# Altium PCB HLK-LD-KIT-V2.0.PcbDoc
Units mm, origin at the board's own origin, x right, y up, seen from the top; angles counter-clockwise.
Board outline 40.5 x 27.7 mm, 2 copper layers (Top Layer, Bottom Layer); 31 components, 15 nets, 118 pads, 48 vias.
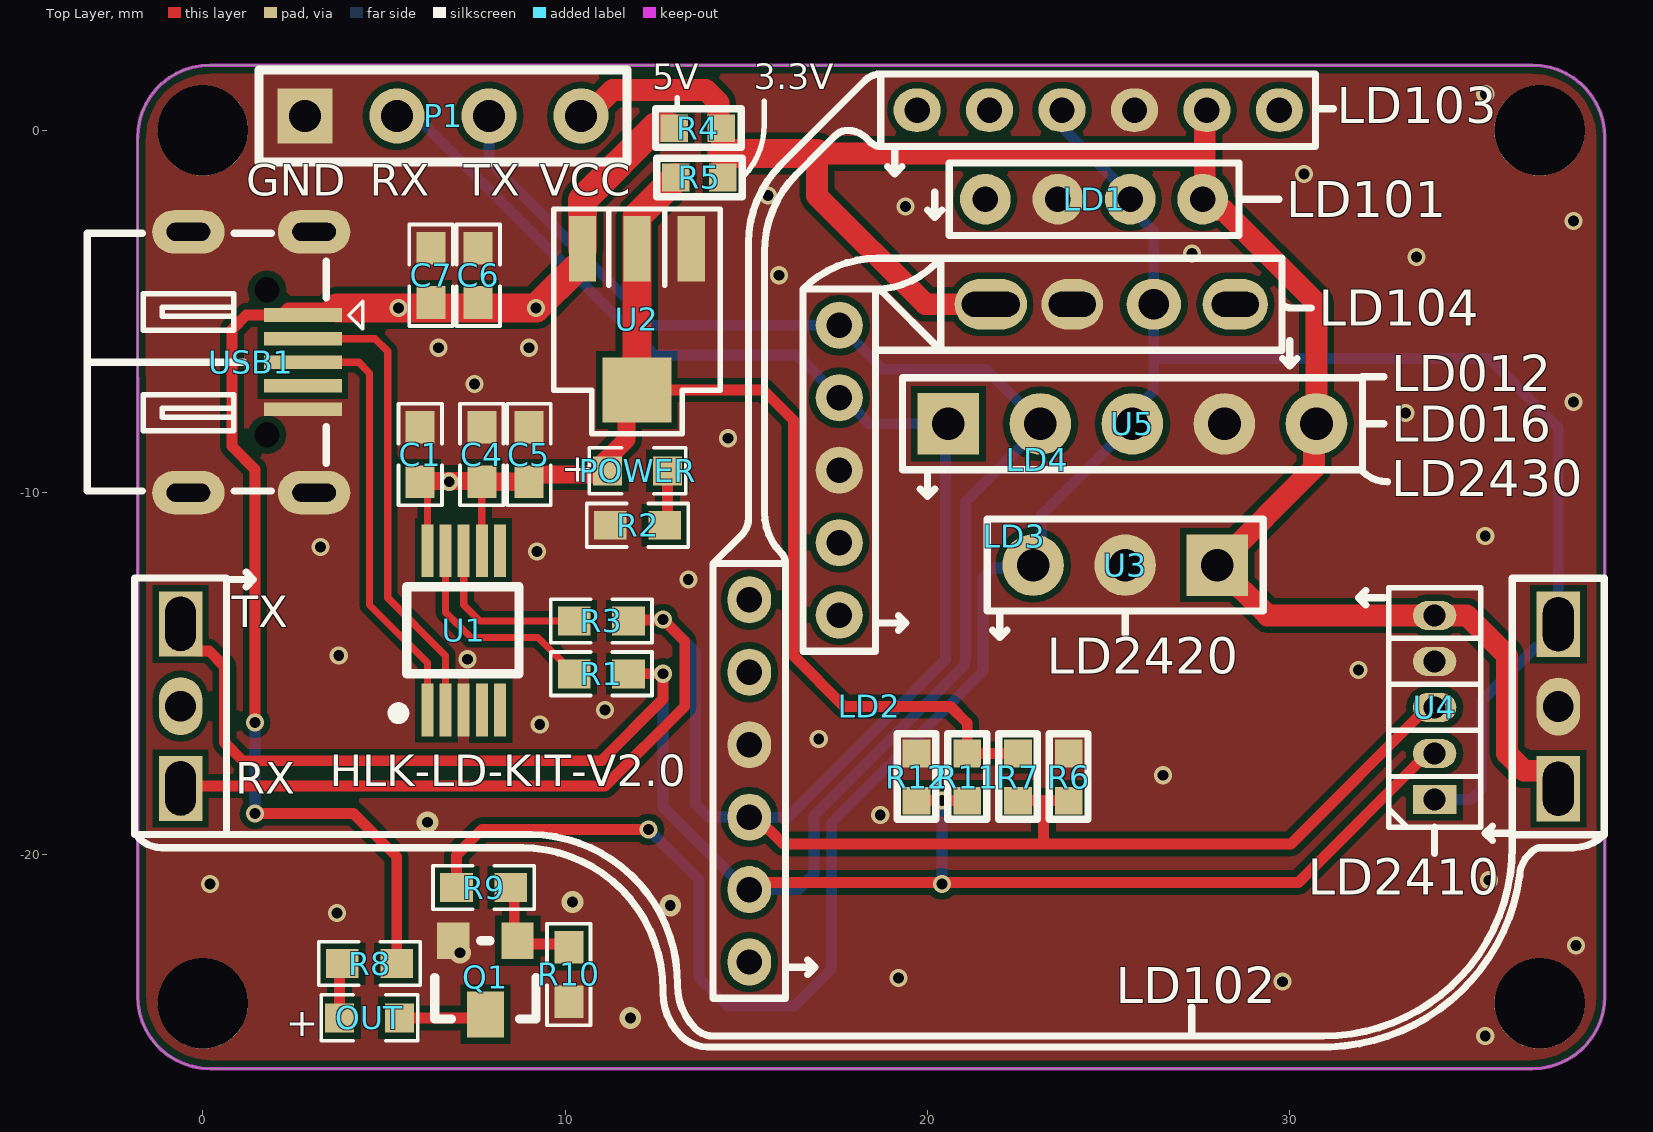
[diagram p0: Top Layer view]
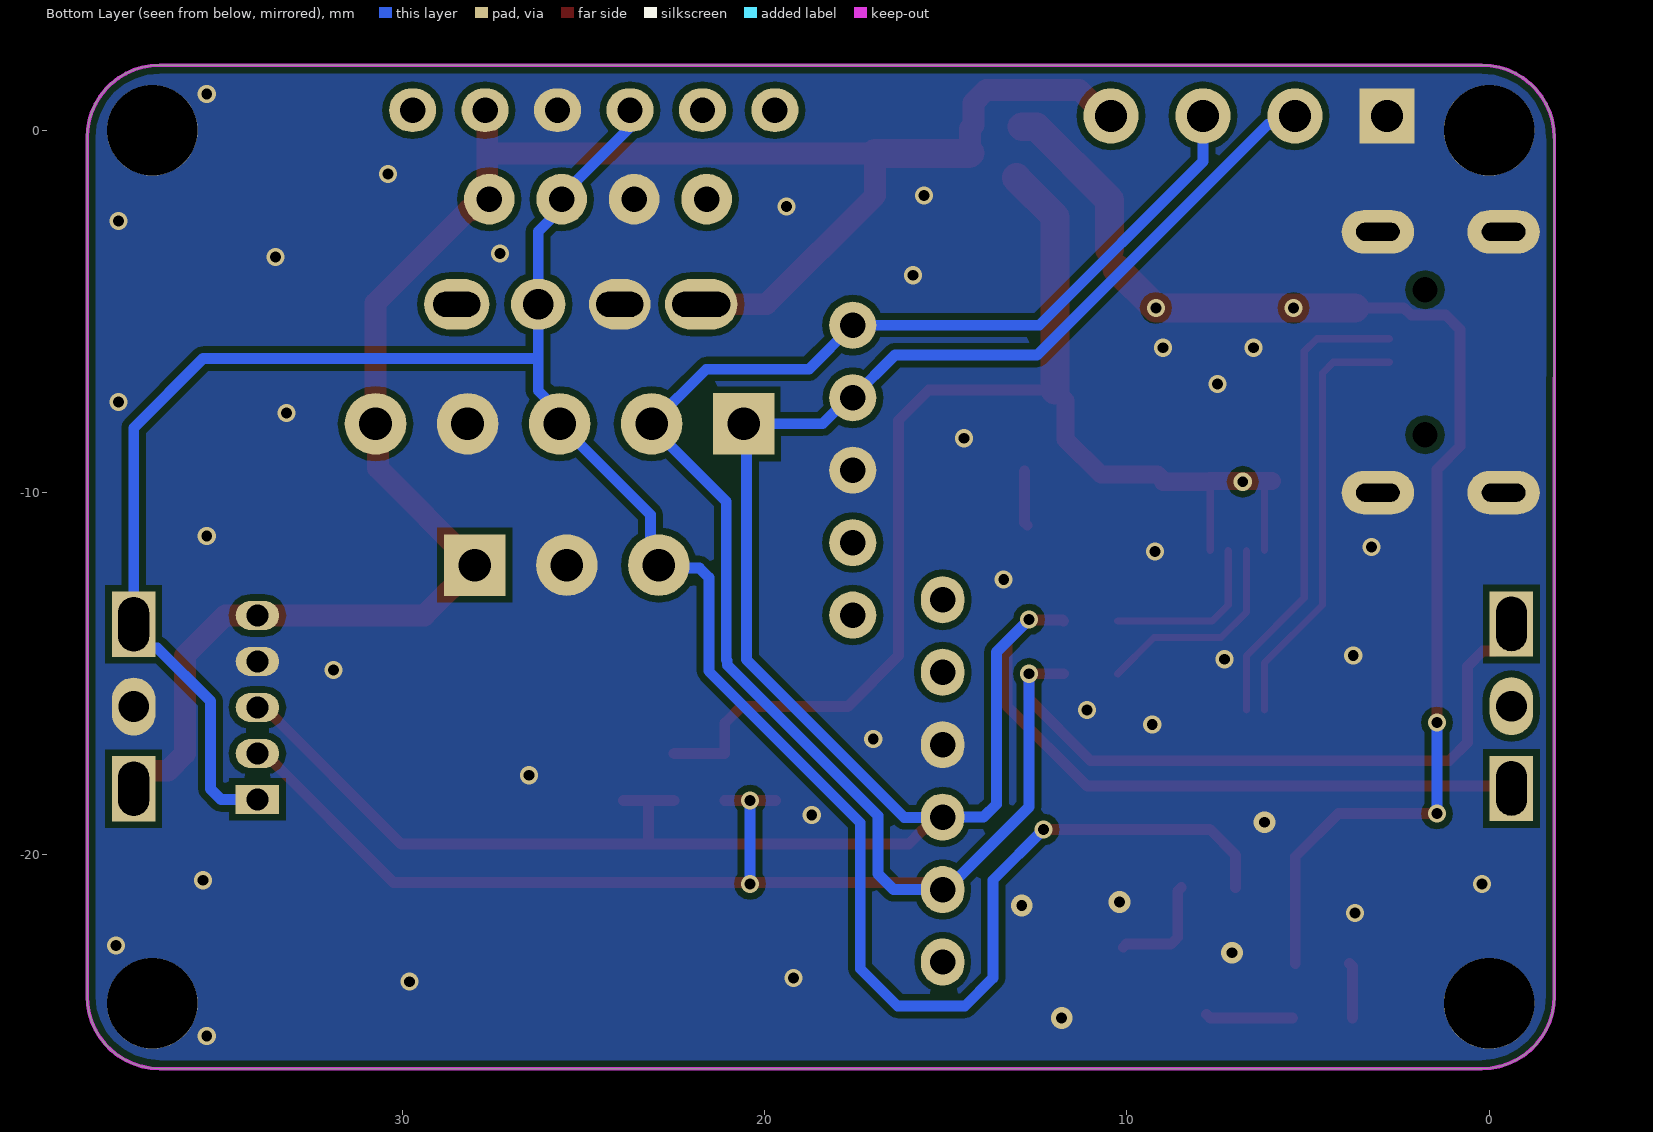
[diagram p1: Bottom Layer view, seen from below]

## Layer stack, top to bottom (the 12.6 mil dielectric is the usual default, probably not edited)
Top Solder: solder mask 0.0102, Solder Resist, Dk 3.5
Top Layer: signal copper 0.0356
Dielectric1: dielectric 0.32, FR-4, Dk 4.8
Bottom Layer: signal copper 0.0356
Bottom Solder: solder mask 0.0102, Solder Resist, Dk 3.5

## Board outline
-1.8,-23.9 -1.8,-0.2 cw(c0.2,-0.2) 0.2,1.8 36.7,1.8 cw(c36.7,-0.2) 38.7,-0.2 38.7,-23.9 cw(c36.7,-23.9) 36.7,-25.9 0.2,-25.9 cw(c0.2,-23.9)

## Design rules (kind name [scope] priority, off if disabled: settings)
Clearance [All] p1: gap=0.18 ignorepadtopadclearanceinfootprint=FALSE except(0: Arc-Hole Track-Hole SMDPad-Hole THPad-Hole Via-Hole Fill-Hole Poly-Hole Region-Hole Text-Hole)
FabricationTestPointUsage TestPointUsage [All] p1: valid=0 allowmultiple=FALSE
FabricationTestpoint Testpoint [(IsPad And (OnTopLayer Or OnBottomLayer))] p1: side=3 testpointundercomponent=TRUE minsize=1.016 maxsize=2.54 preferedsize=1.524 minholesize=0 maxholesize=1.016 preferedholesize=0.813 testpointgrid=0.025 allowsidetop=TRUE allowsidebottom=TRUE usegrid=TRUE gridtolerance=0
PolygonConnect [All] p1: connectstyle=Direct reliefconductorwidth=0.254 reliefentries=4 polygonreliefangle="90 Angle" airgapwidth=0.254
RoutingVias [All] p1: holewidth=0.3 width=0.5 viastyle="Through Hole" minholewidth=0.3 minwidth=0.5 maxholewidth=0.711 maxwidth=1.27
SilkToSolderMaskClearance SilkscreenOverComponentPads [IsPad] p1: minsilkscreentomaskgap=0.254 clearancetoexposedcopper=TRUE
SolderMaskExpansion [All] p1: expansion=0.102 istentingtop=FALSE
Width 5V [InNet('5V')] p1: maxlimit=2 minlimit=0.3 preferedwidth=0.3
Width [All] p2: maxlimit=2 minlimit=0.2 preferedwidth=0.3
27 further rules are at their usual default settings.

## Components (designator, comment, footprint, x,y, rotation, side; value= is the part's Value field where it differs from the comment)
C1 "0.1uF" 0603 6,-8.95 r270 top
C4 "10uF" 0603 7.7,-8.95 r270 top value=100pF
C5 "0.1uF" 0603 9,-8.95 r270 top value=100pF
C6 "10uF" 0603 7.6,-4 r90 top value=100pF
C7 "0.1uF" 0603 6.3,-4 r90 top value=100pF
LD1 "HLK-LD101" LD101 14.6,-11.9 r0 top locked
LD2 "HLK-LD102" LD102 18.4,-15.9 r180 top locked
LD3 "HLK-LD103" LD103 22.4,-11.2 r90 top locked
LD4 "HLK-LD104" LD104 23.033,-9.09 r0 top locked
OUT "" 0603LED 4.6,-24.5 r0 top
P1 "2.54*4单排插针" SIP_4P_2.54 2.82,0.4 r0 top
POWER "LED" 0603LED 12,-9.4 r0 top
Q1 "3904" SOT-23 8.689,-22.368 r180 top
R1 "1K" 0603 11,-15 r180 top
R2 "1K" 0603 12,-10.9 r180 top
R3 "1K" 0603 11,-13.541 r180 top
R4 "0R" R0603 13.664,0.063 r180 top
R5 "NC/0R" R0603 13.7,-1.3 r180 top
R6 "0R" R0603 23.9,-17.85 r270 top
R7 "0R" R0603 22.5,-17.85 r270 top
R8 "1K" 0603 4.6,-23 r180 top
R9 "4.7K" 0603 7.75,-20.9 r180 top
R10 "47K" 0603 10.1,-23.3 r90 top
R11 "0R" R0603 21.1,-17.85 r270 top
R12 "0R" R0603 19.7,-17.85 r270 top
U1 "CH340E" MSOP-10 7.2,-13.8 r0 top
U2 "AMS1117" 1117 13.5,-3.2 r180 top
U3 "HLK-LD2420" HLK-LD2420 25.46,-12 r0 top
U4 "HLK-LD2410" HLK-LD2410 16.494,-15.6 r0 top locked
U5 "HLK-LD2430" HLK-LD2430 25.66,-8.1 r0 top locked
USB1 "micro usb" USB-MICRO_D -0.4,-6.4 r270 top

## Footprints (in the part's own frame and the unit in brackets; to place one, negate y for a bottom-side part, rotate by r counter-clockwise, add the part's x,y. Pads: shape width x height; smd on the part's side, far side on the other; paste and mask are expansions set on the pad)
0603 [mm]
  rect 0.9x0.8 smd: 1(-0.75,0) 2(0.75,0)
  silkscreen extent -1.4,-0.6 1.4,0.6
0603LED [mm]
  rect 0.8x0.8 smd: 1(-0.826,0) 2(0.826,0)
  silkscreen extent -1.33,-0.64 1.33,0.64
1117 [mm]
  rect 1.9x1.8 smd: 0(1.52,3.97)
  rect 0.75x1.8 smd: 1(0.02,0.07) 2(1.52,0.07) 3(3.02,0.07)
  silkscreen extent -0.78,-1.03 3.82,5.17, body extent -0.73,0.14 3.77,4.14, height 1.5
HLK-LD2410 [mm] "海凌科24G雷达模块"
  rect 1.2x0.8 hole 0.6: 1(17.506,-2.87)
  oval 1.2x0.8 hole 0.6: 2(17.506,-1.6) 3(17.506,-0.33) 4(17.506,0.94) 5(17.506,2.21)
  silkscreen extent 16.24,-3.63 18.78,2.97
HLK-LD2420 [mm] "海凌科24G雷达模块"
  rect 1.7x1.7 hole 0.9: 1(2.54,0)
  round 1.7 hole 0.9: 2(0,0) 3(-2.54,0)
  silkscreen extent -3.81,-1.27 3.81,1.27
HLK-LD2430 [mm] "海凌科24G雷达模块"
  rect 1.7x1.7 hole 0.9: 1(-5.08,0)
  round 1.7 hole 0.9: 2(-2.54,0) 3(0,0) 4(2.54,0) 5(5.08,0)
  silkscreen extent -6.35,-1.27 6.35,1.27
LD101 [mm]
  round 1.4 hole 0.7: 1(13,10) 2(11,10) 3(9,10) 4(7,10)
LD102 [mm]
  rect 1.2x1.8 hole 0.85 slot 1.5 at 90 deg: 1(-19.015,2.275) 3(-19.015,-2.265) 4(19.015,-2.275) 6(19.015,2.265)
  oval 1.2x1.6 hole 0.85: 2(-19.015,0.005) 5(19.015,-0.005)
LD103 [mm]
  oval 1.2x1.3 hole 0.7: 1(11.758,-7.316) 2(11.758,-5.316) 3(11.758,-3.316) 4(11.758,-1.316) 5(11.758,0.684) 6(11.758,2.684)
  oval 1.3x1.2 hole 0.7: 7(-1.758,7.316) 8(-3.758,7.316) 9(-5.758,7.316) 10(-7.758,7.316) 11(-9.758,7.316) 12(-11.758,7.316)
LD104 [mm]
  oval 1.8x1.397 hole 0.7 slot 1.3 at 0 deg: 1(5.467,4.29)
  oval 1.5x1.397 hole 0.85: 2(3.217,4.29)
  oval 1.7x1.397 hole 0.7 slot 1.3 at 0 deg: 3(0.967,4.29)
  oval 2x1.397 hole 0.7 slot 1.6 at 0 deg: 4(-1.283,4.29)
  round 1.3 hole 0.7: 5(-5.467,3.71) 6(-5.467,1.71) 7(-5.467,-0.29) 8(-5.467,-2.29) 9(-5.467,-4.29)
MSOP-10 [mm]
  rect 0.33x1.45 smd: 1(-1,-2.2) 2(-0.5,-2.2) 3(0,-2.2) 4(0.5,-2.2) 5(1,-2.2) 6(1,2.2) 7(0.5,2.2) 8(0,2.2) 9(-0.5,2.2) 10(-1,2.2)
  silkscreen extent -1.95,-2.44 1.53,1.2
R0603 [mil] "1/10W贴片电阻"
  rect 30x30 smd mask+2: 1(-25.59,0) 2(25.59,0)
  silkscreen extent -47,-21 46,21, body extent -31,-16 32,16, height 16
SIP_4P_2.54 [mil]
  rect 60x60 / inner round 60 / far side rect 60x60 hole 35: 1(0,0)
  round 60 hole 35: 2(100,0) 3(200,0) 4(300,0)
  silkscreen extent -50,-50 350,50
SOT-23 [mil]
  rect 35x40 smd: 1(0,0) 2(70,0)
  rect 40x50 smd: 3(35,80)
  silkscreen extent -20,0 90,85
USB-MICRO_D [mm] "micro型USB ，6.7*7.5*2.5mm"
  round 0 hole 0.7 unplated: 0(-2,2.17) 0(2,2.17)
  rect 0.381x2.15 smd: 1(-1.3,3.16) 2(-0.65,3.16) 3(0,3.16) 4(0.65,3.16) 5(1.3,3.16)
  oval 1.2x2 hole 0.5 slot 1.2 at 90 deg: 6(3.6,3.47) 7(3.6,0) 8(-3.6,0) 9(-3.6,3.47)
  silkscreen extent -3.56,-2.79 3.56,4.81

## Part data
C1: library part CAP, "Capacitor"
C4 C5 C6 C7: library part Cap, "Capacitor"
LD1: library part LD101
LD2 LD3 LD4: library part HLK-LD015-5G
OUT: library part LED
P1: library part 2.54*2插针
Q1: library part A09T, "NPN General Purpose Amplifier", PackageDocument=Sep-1998
R1 R2 R3 R8 R9 R10: library part Res1, "Resistor"
R4 R5 R6 R7 R11 R12: library part R
U2: library part Component_1
U3 U4 U5: "生命存在24G雷达"
USB1: library part USB-D

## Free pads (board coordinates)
  round 2.5 hole 2.5: 0(0,-24.1) 0(36.9,0) 2(0,0) 2(36.9,-24.1)

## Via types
v1: diameter 0.5, hole 0.3, Top Layer to Bottom Layer, tented both sides, 43 vias
v2: diameter 0.6, hole 0.3, Top Layer to Bottom Layer, tented both sides, 5 vias

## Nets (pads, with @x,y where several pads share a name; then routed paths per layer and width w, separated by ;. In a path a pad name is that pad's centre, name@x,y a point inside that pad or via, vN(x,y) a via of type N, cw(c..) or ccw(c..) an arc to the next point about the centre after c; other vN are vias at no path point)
5V: C6.1 C7.1 R4.2 R8.1 U2.3 USB1.1 | length 35.8
  Top Layer w0.3: v1(1.44,-18.86) 4.16,-18.86 5.35,-20.05 R8.1 ; v1(1.44,-16.347) 1.44,-9.359 0.8,-8.719 0.8,-5.497 1.197,-5.1 2.15,-5.1 2.35,-4.9 3.7,-4.9
  Top Layer w0.8: 3.7,-4.9 v1(5.4,-4.9) v1(9.2,-4.9) U2.3@10.275,-3.825 ; U2.3 10.48,-1.92 12.5,0.1 R4.2@12.9,0.1
  Bottom Layer w0.3: v1(1.44,-18.86) v1(1.44,-16.347)
DM: U1.2 USB1.2 | length 13
  Top Layer w0.2: USB1.2 4.75,-5.75 5.1,-6.1 5.1,-12.9 6.7,-14.5 U1.2
DP: U1.1 USB1.3 | length 11.9
  Top Layer w0.203: USB1.3 4.3,-6.4 4.6,-6.7 4.6,-13.1 6.2,-14.7 U1.1
GND: C1.1 C4.1 C5.1 C6.2 C7.2 LD1.3 LD2.2 LD3.3 LD3.9 LD4.3 LD4.7 P1.1 pad.0 pad.2 Q1.2 R2.2 R6.1 R10.1 R12.1 U1.3 U2.1 U3.2 U4.4 U5.4 USB1.5 USB1.6 USB1.7 USB1.8 USB1.9
  other v1: 35.4,-25 29.8,-23.5 19.2,-23.4 37.9,-22.5 3.7,-21.6 0.2,-20.8 35.5,-20.7 18.7,-18.9 26.5,-17.8 17,-16.8 9.3,-16.4 11.1,-16 31.9,-14.9 7.3,-14.6 3.75,-14.5 13.4,-12.4 9.222,-11.627 3.25,-11.5 35.4,-11.2 14.5,-8.5 33.2,-7.8 37.84,-7.5 7.5,-7 6.5,-6 9,-6 15.9,-4 33.5,-3.5 27.3,-3.4 37.84,-2.5 19.4,-2.1 15.6,-1.8 30.4,-1.2 35.4,1
  other v2: 11.8,-24.5 7.1,-22.7 12.9,-21.4 10.2,-21.3 6.2,-19.1
NetOUT_1: OUT.1 R8.2 | length 1.5
  Top Layer w0.3: OUT.1 3.775,-23.075 R8.2
NetOUT_2: OUT.2 Q1.3 | length 2.4
  Top Layer w0.3: OUT.2 7.7,-24.5 Q1.3
NetPOWER_2: POWER.2 R2.1 | length 1.5
  Top Layer w0.3: R2.1 12.825,-10.825 POWER.2
NetQ1_1: Q1.1 R9.1 R10.2 | length 3
  Top Layer w0.3: R9.1 8.595,-20.994 8.595,-22.274 Q1.1 8.78,-22.459 10.009,-22.459 R10.2
OUT: LD1.2 LD2.3 LD3.4 LD4.2 R9.2 U3.3 U4.1 U5.3 | length 69.2
  Top Layer w0.3: R9.2 7,-20 7.7,-19.3 v1(12.3,-19.3)
  Bottom Layer w0.3: v1(12.3,-19.3) 13.7,-20.7 13.7,-23.4 14.476,-24.176 16.324,-24.176 17.358,-23.142 17.358,-19.113 21.512,-14.959 21.512,-14.945 21.539,-14.918 21.539,-12.341 21.796,-12.085 22.835,-12.085 23.15,-11.77 23.15,-10.61 U5.3 25.66,-7.775 26.25,-7.185 26.25,-6.3 ; LD3.4@23.7,0.742 23.7,0.1 25.6,-1.8 LD1.2 25.6,-2.144 26.25,-2.794 LD4.2 26.25,-6.3 ; U4.1 35.007,-18.47 35.3,-18.177 35.3,-15.75 36.765,-14.285 37.065,-14.285 37.415,-13.935 LD2.3 37.415,-8.215 35.5,-6.3 26.25,-6.3
RX: LD2.6 LD3.10 LD4.6 P1.2 R3.1 R6.2 R7.2 U4.3 U5.1 | length 81.6
  Top Layer w0.3: LD2.6 -0.55,-18.1 11.1,-18.1 13.3,-15.9 13.3,-14.1 v1(12.7,-13.5) 12.679,-13.521 11.771,-13.521 R3.1 ; LD3.10@15.084,-18.764 15.645,-19.325 15.652,-19.325 16.023,-19.696 23.2,-19.696 ; R7.2 23.2,-18.5 ; R6.2 23.2,-18.5 ; U4.3 33.8,-15.93 30.034,-19.696 23.2,-19.696 ; 23.2,-19.696 23.2,-18.5
  Bottom Layer w0.3: P1.2 5.594,0.166 6.11,0.166 12.476,-6.2 16.4,-6.2 17.566,-7.366 LD4.6 17.682,-7.38 18.402,-8.1 U5.1 20.504,-8.176 20.504,-14.609 16.144,-18.97 15.096,-18.97 LD3.10 13.958,-18.958 13.6,-18.6 13.6,-14.4 v1(12.7,-13.5)
RX0_CH340: R1.2 U1.9 | length 6
  Top Layer w0.2: U1.9 6.7,-12.4 6.7,-13.3 7.4,-14 9.25,-14 R1.2
TX: LD2.4 LD3.11 LD4.5 P1.3 R1.1 R11.2 R12.2 U4.2 U5.2 | length 86.1
  Top Layer w0.3: LD2.4 -0.615,-13.925 -0.165,-14.375 0.175,-14.375 0.6,-14.8 0.6,-16.9 1.1,-17.4 11,-17.4 12.7,-15.7 v1(12.7,-15) R1.1 ; LD3.11@15.084,-20.758 20.4,-20.758 30.242,-20.758 33.8,-17.2 U4.2 ; R12.2 v1(20.4,-18.5) R11.2
  Bottom Layer w0.3: P1.3@7.9,0.3 7.9,-0.863 12.417,-5.38 LD4.5 18.778,-6.592 21.612,-6.592 U5.2 23.12,-8.18 21.059,-10.241 21.059,-14.612 21.032,-14.639 21.032,-14.76 16.873,-18.919 16.873,-20.527 16.442,-20.958 LD3.11 14.981,-20.958 12.7,-18.677 v1(12.7,-15) ; v1(20.4,-20.8) v1(20.4,-18.5)
TX0_CH340: R3.2 U1.8 | length 4.7
  Top Layer w0.2: U1.8 7.2,-13.1 7.641,-13.541 R3.2
V3.3: C1.2 C4.2 C5.2 POWER.1 R5.2 R7.1 R11.1 U1.7 U1.10 U2.0 U2.2 | length 36.8
  Top Layer w0.2: C1.2 6.2,-9.9 U1.10 ; U1.7 C4.2@7.7,-9.8
  Top Layer w0.3: C4.2 C4.2@7.75,-9.75 ; U2.0 15.47,-7.17 16.3,-8 16.3,-14.5 17.7,-15.9 20.636,-15.9 21.1,-16.364 R11.1 R7.1
  Top Layer w0.5: C1.2@6,-9.674 7.7,-9.674 7.726,-9.7 C5.2 9,-9.65 9.15,-9.5 10.719,-9.5 11.692,-8.527 11.692,-7.458 U2.0
  Top Layer w0.8: U2.0 U2.2 11.98,-2.385 13.05,-1.315 R5.2
  other v1: 6.8,-9.7
VCC: LD1.1 LD2.1 LD3.2 LD4.4 P1.4 R4.1 R5.1 U3.1 U4.5 U5.5 | length 55.2
  Top Layer w0.6: P1.4@10.5,0.4 10.6,0.4 11.318,1.118 13.882,1.118 14.233,0.766 14.233,0.144 R4.1 14.332,0.045 14.332,-0.618 ; LD4.4 19.95,-4.8 16.95,-1.8 16.95,-0.639 27.658,-0.639 ; LD3.2@27.658,0.7 27.658,-0.639 ; LD2.1 37.415,-17.875 37.215,-17.675 36.469,-17.675 36,-17.206 36,-14.5 34.89,-13.39 U4.5 29.39,-13.39 U3.1 30.67,-9.33 30.67,-8.17 U5.5 30.74,-4.757 28.183,-2.2 28.062,-2.2 27.762,-1.9 LD1.1 27.658,-1.842 27.658,-0.639
  Top Layer w0.8: 14.332,-0.618 14.353,-0.639 16.95,-0.639
pads on no net: LD1.4 LD2.5 LD3.1 LD3.5 LD3.6 LD3.7 LD3.8 LD3.12 LD4.1 LD4.8 LD4.9 U1.4 U1.5 U1.6 USB1.0 USB1.4

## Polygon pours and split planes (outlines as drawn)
GND on Top Layer "NONET_L02_P-001" (solid, pour order 0): -1.8,-23.9 -1.8,-25.1 -1,-25.9 37.9,-25.9 38.7,-25.1 38.7,-0.2 38.7,1.2 38.1,1.8 -1.2,1.8 -1.8,1.2 -1.8,-0.2
GND on Bottom Layer "NONET_L02_P-001" (solid, pour order 1): -1.8,-23.9 -1.8,-25.1 -1,-25.9 37.9,-25.9 38.7,-25.1 38.7,-0.2 38.7,1.2 38.1,1.8 -1.2,1.8 -1.8,1.2 -1.8,-0.2

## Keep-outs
Keep-Out Layer:
  lines w0.08: -1.8,-6.826 -1.8,-0.2
  lines w0.1: -1.8,-6.826 -1.8,-23.9 ccw(c0.2,-23.9) 0.2,-25.9 36.7,-25.9 ccw(c36.7,-23.9) 38.7,-23.9 38.7,-0.2 ccw(c36.7,-0.2) 36.7,1.8 0.2,1.8 ccw(c0.2,-0.2) -1.8,-0.2

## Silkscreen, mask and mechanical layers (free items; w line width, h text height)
Top Overlay:
  lines w0.15: 13.1,0.6 13.1,0.9 ; 14.894,-1.3 ccw(c13.43,0.163) 15.5,0.163 15.5,0.8
  lines w0.2: -1.885,-12.39 -1.885,-19.435 0.655,-19.435 ; -1.885,-12.355 0.655,-12.355 0.655,-15.895 0.655,-19.435 ; -1.8,-19.435 ccw(c-1.643,-19.435) -1.754,-19.546 ccw(c-1.141,-18.933) -1.141,-19.8 8.83,-19.8 ; 0.7,-12.4 1.4,-12.4 ; 1.2,-12.6 1.4,-12.4 ; 1.2,-12.2 1.4,-12.4 ; 8.8,-19.8 cw(c8.784,-23.716) 12.7,-23.731 ; 12.7,-23.67 12.7,-23.793 ccw(c14.407,-23.793) 13.2,-25 ccw(c13.924,-24.276) 13.924,-25.3 31.13,-25.3 ccw(c30.915,-19.815) 36.349,-20.593 cw(c37.173,-20.593) 36.59,-20.01 36.7,-19.9 cw(c36.941,-20.141) 36.941,-19.8 37.307,-19.8 37.828,-19.8 ccw(c37.828,-18.588) 38.685,-19.445 ; 13.1,-23.47 13.1,-23.593 ; 16.2,-23.1 16.9,-23.1 ; 16.7,-23.3 16.9,-23.1 ; 16.7,-22.9 16.9,-23.1 ; 18.6,-6.1 cw(c18.672,-6.172) 18.672,-6.07 20.371,-6.07 ; 18.7,-13.6 19.4,-13.6 ; 18.9,-1 19.1,-1.2 ; 19.1,-0.5 19.1,-1.2 ; 19.2,-13.8 19.4,-13.6 ; 19.2,-13.4 19.4,-13.6 ; 19.3,-1 19.1,-1.2 ; 19.8,-9.9 20,-10.1 ; 20,-9.4 20,-10.1 ; 20,-2.2 20.2,-2.4 ; 20.2,-9.9 20,-10.1 ; 20.2,-1.7 20.2,-2.4 ; 20.4,-2.2 20.2,-2.4 ; 21.8,-13.8 22,-14 ; 22,-13.3 22,-14 ; 22.2,-13.8 22,-14 ; 25.46,-13.9 25.46,-13.27 ; 27.3,-25 27.3,-24.2 ; 28.6,-1.9 29.7,-1.9 ; 29.79,-4.8 ccw(c30.031,-4.559) 30.031,-4.9 30.6,-4.9 ; 29.8,-6.3 30,-6.5 ; 30,-5.8 30,-6.5 ; 30.2,-6.3 30,-6.5 ; 30.716,0.558 cw(c30.817,0.457) 30.817,0.6 31.2,0.6 ; 32,-6.8 32.6,-6.8 ; 32.017,-9.417 ccw(c32.7,-8.734) 32.7,-9.7 ; 32.1,-13.1 31.9,-12.9 ; 32.1,-12.7 31.9,-12.9 ; 32.6,-12.9 31.9,-12.9 ; 32.6,-8.1 32.01,-8.1 ; 34,-19.962 34,-19.232 ; 35.6,-19.6 35.4,-19.4 ; 35.6,-19.2 35.4,-19.4 ; 36.1,-19.4 35.4,-19.4 ; 36.145,-12.4 36.145,-19.445 ; 36.145,-12.365 38.685,-12.365 38.685,-15.905 38.685,-19.445 ; 0.655,-19.435 9.065,-19.435 cw(c9.004,-23.531) 13.1,-23.593 ; 1.4,-12.4 1.4,-12.4 ; 13.1,-23.593 ccw(c14.807,-23.593) 13.6,-24.8 ccw(c14.083,-24.317) 14.083,-25 30.93,-25 ccw(c30.93,-19.785) 36.145,-19.785 36.145,-19.445 ; 14.084,-11.958 14.873,-11.169 ccw(c14.417,-10.713) 15.062,-10.713 15.062,-6.7 15.062,-3.108 cw(c18.128,-3.108) 15.96,-0.94 18.276,1.376 cw(c18.716,0.936) 18.716,1.558 ; 14.084,-11.958 14.084,-23.958 16.084,-23.958 16.084,-11.958 ; 14.084,-11.958 16.084,-11.958 ; 15.962,-11.662 cw(c17.076,-10.547) 15.5,-10.547 15.5,-3.37 cw(c18.566,-3.37) 16.398,-1.202 17.1,-0.5 17.459,-0.141 cw(c17.8,-0.483) 17.8,0 cw(c17.8,-0.724) 18.312,-0.212 18.419,-0.319 ccw(c18.716,-0.023) 18.716,-0.442 ; 15.962,-11.662 cw(c15.665,-11.958) 16.084,-11.958 ; 15.962,-11.662 15.962,-11.662 ; 16.566,-4.38 cw(c18.618,-6.432) 18.618,-3.53 20.371,-3.53 ; 16.566,-4.38 16.566,-14.38 18.566,-14.38 18.566,-4.38 ; 16.566,-4.38 18.566,-4.38 ; 16.9,-23.1 16.9,-23.1 ; 18.566,-4.38 cw(c18.566,-4.658) 18.762,-4.461 20.371,-6.07 ; 18.566,-4.38 ccw(c18.566,-2.074) 20.196,-3.705 20.371,-3.53 ; 18.716,-0.442 30.716,-0.442 30.716,1.558 18.716,1.558 ; 18.716,-0.442 18.716,1.558 ; 19.1,-1.2 19.1,-1.2 ; 20,-10.1 20,-10.1 ; 20.2,-2.4 20.2,-2.4 ; 20.371,-6.07 20.371,-3.53 ; 20.371,-6.07 25.25,-6.07 29.79,-6.07 29.79,-3.53 26.25,-3.53 20.371,-3.53 ; 22,-14 22,-14 ; 28.6,-0.9 ccw(c28.6,-0.9) 28.6,-0.9 ; 28.6,-0.9 20.6,-0.9 20.6,-2.9 28.6,-2.9 28.6,-0.9 ; 31.9,-12.9 31.9,-12.9 ; 32.01,-8.1 ccw(c32.01,-8.1) 32.01,-8.1 ; 35.4,-19.4 35.4,-19.4 ; 36.145,-19.445 38.685,-19.445
  text "5V" at 12.4,0.9 h1.2
  text "3.3V" at 15.2,0.897 h1.2
  text "LD103" at 31.3,0.2 h1
  text "GND" at 1.2,-2.1 h1.5
  text "RX" at 4.6,-2.1 h1.5
  text "TX" at 7.2,-2.1 h1.5
  text "VCC" at 9.3,-2.1 h1.5
  text "LD101" at 29.9,-2.4 h1
  text "LD104" at 30.8,-5.4 h1
  text "LD012" at 32.8,-7.2 h1
  text "LD016" at 32.8,-8.6 h1
  text "LD2430" at 32.8,-10.1 h1
  text "TX" at 0.8,-14 h1.5
  text "LD2420" at 23.3,-15 h1
  text "HLK-LD-KIT-V2.0" at 3.5,-18.4 h1.5
  text "RX" at 0.9,-18.6 h1.5
  text "LD2410" at 30.5,-21.1 h1
  text "LD102" at 25.2,-24.1 h1
Top Solder:
  rectangle: 5.9,-16.9 8.5,-15.1
  rectangle: 5.9,-12.5 8.5,-10.7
